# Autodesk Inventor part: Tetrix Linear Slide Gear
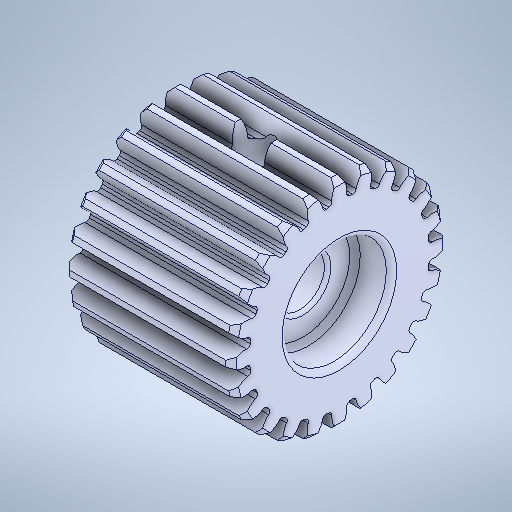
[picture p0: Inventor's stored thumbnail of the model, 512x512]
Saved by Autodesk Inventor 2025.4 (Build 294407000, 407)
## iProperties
Created: 2021-10
Part Number: Tetrix Linear Slide Gear
Material: Genérico
Document SubType Name: Modeling
Designer: usuario
Density: 1 g/cm^3
Appearance: Valor por defecto
Author: usuario
Sending System: SolidWorks 2016
Last Author: LENOVO
Last Saved: 2021-10-23
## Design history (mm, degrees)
fillet "Fillet2"
node "Sólido1"
